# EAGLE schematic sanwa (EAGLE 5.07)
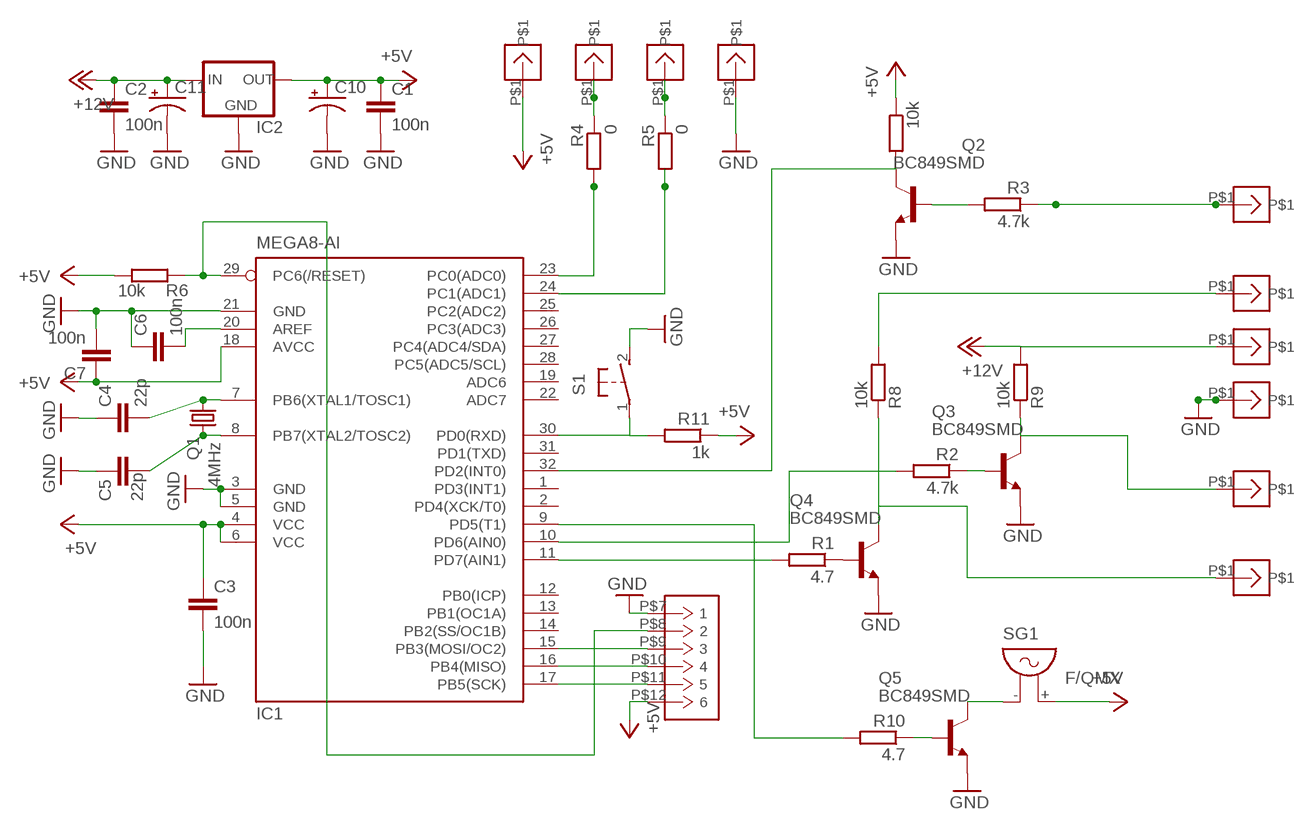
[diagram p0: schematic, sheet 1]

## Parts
C1  100n  C-EUC0805  [C0805]
C2  100n  C-EUC0805  [C0805]
C3  100n  C-EUC0805  [C0805]
C4  22p  C-EUC0603  [C0603]
C5  22p  C-EUC0603  [C0603]
C6  100n  C-EUC0603  [C0603]
C7  100n  C-EUC0603  [C0603]
C10  CPOL-US150CLZ-0810  [150CLZ-0810]
C11  CPOL-US150CLZ-0810  [150CLZ-0810]
IC1  MEGA8-AI  [TQFP32-08-04]
IC2  78LXX  [78LXX]
Q1  4MHz  CRYTALHC49S  [HC49/S]
Q2  BC849SMD  [SOT23-BEC]
Q3  BC849SMD  [SOT23-BEC]
Q4  BC849SMD  [SOT23-BEC]
Q5  BC849SMD  [SOT23-BEC]
R1  4.7  R-EU_R0603  [R0603]
R2  4.7k  R-EU_R0603  [R0603]
R3  4.7k  R-EU_R0603  [R0603]
R4  0  R-EU_M0805  [M0805]
R5  0  R-EU_M0805  [M0805]
R6  10k  R-EU_R0603  [R0603]
R7  10k  R-EU_R0603  [R0603]
R8  10k  R-EU_R0603  [R0603]
R9  10k  R-EU_R0603  [R0603]
R10  4.7  R-EU_R0603  [R0603]
R11  1k  R-EU_R0603  [R0603]
S1  31-XX  [B3F-31XX]
SG1  F/QMX  [F/QMX]
U$1  1PIN  [1PIN]
U$2  1PIN  [1PIN]
U$3  6PIN6  [6PIN]
U$4  1PIN  [1PIN]
U$5  1PIN  [1PIN]
U$6  1PIN  [1PIN]
U$7  1PIN  [1PIN]
U$8  1PIN  [1PIN]
U$9  1PIN  [1PIN]
U$10  1PIN  [1PIN]
U$11  1PIN  [1PIN]

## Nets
+5V: C1.1 C3.1 C7.1 C10.+ IC1.4(VCC) IC1.6(VCC) IC1.18(AVCC) IC2.OUT R6.1 R7.1 R11.1 SG1.+ U$3.P$12 U$10.P$1
+12V: C2.1 C11.+ IC2.IN R9.2 U$5.P$1
GND: C1.2 C2.2 C3.2 C4.1 C5.1 C6.1 C7.2 C10.- C11.- IC1.3(GND) IC1.5(GND) IC1.21(GND) IC2.GND Q2.E Q3.E Q4.E Q5.E S1.2(S) U$3.P$7 U$6.P$1 U$9.P$1
N$1: Q5.B R10.1
N$2: R8.2 U$11.P$1
N$3: IC1.15(PB3(MOSI/OC2)) U$3.P$9
N$4: IC1.17(PB5(SCK)) U$3.P$11
N$5: Q2.B R3.2
N$6: IC1.16(PB4(MISO)) U$3.P$10
N$7: IC1.29(PC6(/RESET)) R6.2 U$3.P$8
N$8: IC1.30(PD0(RXD)) R11.2 S1.1(P)
N$9: IC1.11(PD7(AIN1)) R1.2
N$10: Q4.B R1.1
N$11: R3.1 U$1.P$1
N$13: R4.1 U$7.P$1
N$14: IC1.23(PC0(ADC0)) R4.2
N$15: IC1.24(PC1(ADC1)) R5.2
N$16: IC1.9(PD5(T1)) R10.2
N$17: Q4.C R8.1 U$2.P$1
N$18: IC1.10(PD6(AIN0)) R2.2
N$19: Q3.B R2.1
N$20: Q3.C R9.1 U$4.P$1
N$22: C4.2 IC1.7(PB6(XTAL1/TOSC1)) Q1.2
N$23: C5.2 IC1.8(PB7(XTAL2/TOSC2)) Q1.1
N$24: R5.1 U$8.P$1
N$26: Q5.C SG1.-
N$27: C6.2 IC1.20(AREF)
N$28: IC1.32(PD2(INT0)) Q2.C R7.2
Unconnected: IC1.1(PD3(INT1)) IC1.2(PD4(XCK/T0)) IC1.12(PB0(ICP)) IC1.13(PB1(OC1A)) IC1.14(PB2(SS/OC1B)) IC1.19(ADC6) IC1.22(ADC7) IC1.25(PC2(ADC2)) IC1.26(PC3(ADC3)) IC1.27(PC4(ADC4/SDA)) IC1.28(PC5(ADC5/SCL)) IC1.31(PD1(TXD))

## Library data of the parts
C1-C7 = rcl:C-EU: CAPACITOR, European symbol
C10 C11 = rcl:CPOL-US: POLARIZED CAPACITOR, American symbol
IC1 = atmel:MEGA8: MICROCONTROLLER 8 Kbytes FLASH, 1 kbytes SRAM, 512 bytes EEPROM, USART, 6-channel 10 bit ADC, 2-channel 8 bit ADC Pin compatible with Atmega48, ATMega88, ATMega168 Source: avr.lbr
IC2 = v-reg:78LXX: VOLTAGE REGULATOR
Q1 = crystal:CRYTAL: CRYSTAL
Q2-Q5 = transistor-npn:BC849*: NPN Transistor
R1-R11 = rcl:R-EU_: RESISTOR, European symbol
S1 = switch-omron:31-XX: OMRON SWITCH
SG1 = buzzer:F/QMX: BUZZER
U$1 U$2 U$4-U$11 = 001xx:1PIN
U$3 = 001xx:6PIN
